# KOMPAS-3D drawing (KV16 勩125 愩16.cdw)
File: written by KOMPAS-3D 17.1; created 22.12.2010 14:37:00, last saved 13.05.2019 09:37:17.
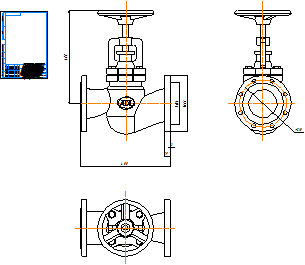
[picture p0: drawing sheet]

Title block, sheet 1: name: KV16 Ду125 Ру16; material: Внимание! Данный продукт является объектом авторского права ООО «Торговый Дом АДЛ». / Запрещается изменение, копирование, распространение / (в том числе путем копирования на другие сайты и ресурсы в Интернете) / или любое иное использование информации и объектов без предварительного / согласия правообладателя (ООО «Торговый Дом АДЛ»).; scale: 1:1; sheets: 1; organisation: ООО "Торговый дом АДЛ"; sheet format: A4; stored path: \\adlc.lan\data\АДЛ_ПКД\3D-модели\ADL production\Вентили ГРАНВЕНТ\KV16\KOMPAS 2D\KV16 Ду125 Ру16.cdw

Views: Спереди 1, Проекционный вид 2, Вид 5
Dimensions and other numbers on the sheet: 184; 250; 400; 3; 29; 411; 210; 1:1; 1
